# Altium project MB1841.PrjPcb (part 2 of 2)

## Sheet STLink_V3EC.SchDoc: STLINK-V3EC
size A3; Date: Not used; ApprovedBy: Not used; CheckedBy: Not used; Author: Not used; CompanyName: STMicroelectronics; DrawnBy: Not used; Engineer: Not used; Organization: Not used; Address1: Not used; Address2: Not used; Address3: Not used; Address4: Not used; DocumentNumber: 8; Revision: Not used; SheetNumber: 8; SheetTotal: 9
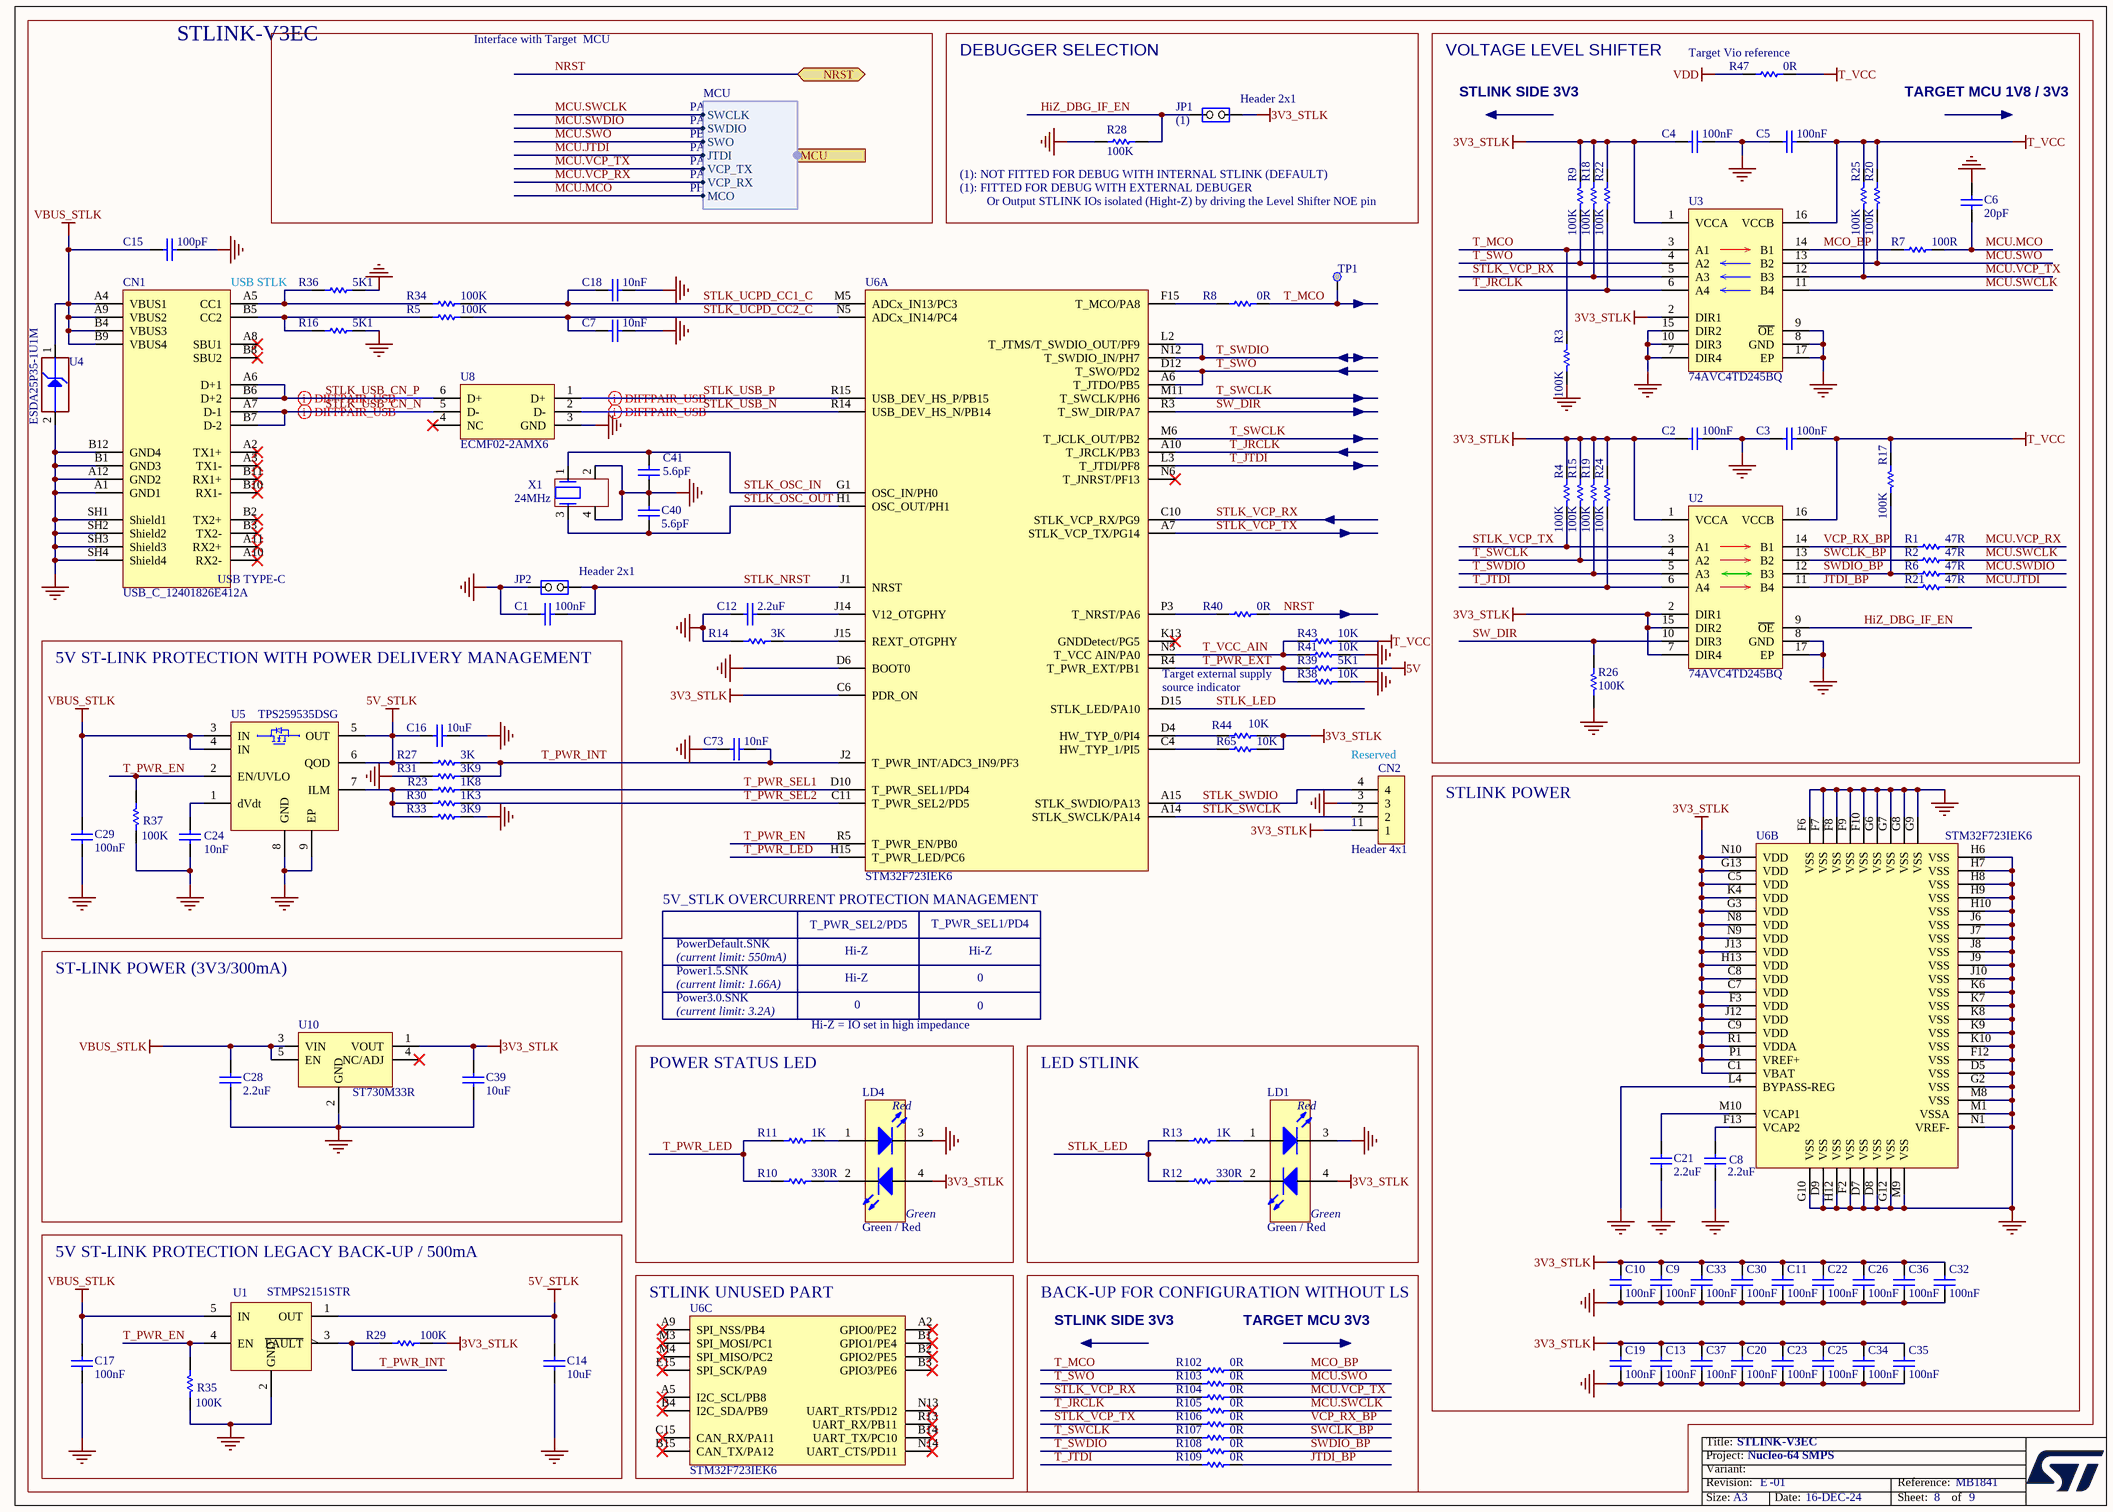
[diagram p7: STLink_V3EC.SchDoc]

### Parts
C1  value 100nF  [C0402]  (hidden comment: Capacitor)
C2  value 100nF  [C0402]  (hidden comment: Capacitor)
C3  value 100nF  [C0402]  (hidden comment: Capacitor)
C4  value 100nF  [C0402]  (hidden comment: Capacitor)
C5  value 100nF  [C0402]  (hidden comment: Capacitor)
C6  value 20pF  [C0402]  (hidden comment: Capacitor)
C7  value 10nF  [C0402]  (hidden comment: Capacitor)
C8  value 2.2uF  [C0402]  (hidden comment: Capacitor)
C9  value 100nF  [C0402]  (hidden comment: Capacitor)
C10  value 100nF  [C0402]  (hidden comment: Capacitor)
C11  value 100nF  [C0402]  (hidden comment: Capacitor)
C12  value 2.2uF  [C0402]  (hidden comment: Capacitor)
C13  value 100nF  [C0402]  (hidden comment: Capacitor)
C14  value 10uF  [C0603]  (hidden comment: Capacitor)
C15  value 100pF  [C0402]  (hidden comment: Capacitor)
C16  value 10uF  [C0603]  (hidden comment: Capacitor)
C17  value 100nF  [C0402]  (hidden comment: Capacitor)
C18  value 10nF  [C0402]  (hidden comment: Capacitor)
C19  value 100nF  [C0402]  (hidden comment: Capacitor)
C20  value 100nF  [C0402]  (hidden comment: Capacitor)
C21  value 2.2uF  [C0402]  (hidden comment: Capacitor)
C22  value 100nF  [C0402]  (hidden comment: Capacitor)
C23  value 100nF  [C0402]  (hidden comment: Capacitor)
C24  value 10nF  [C0402]  (hidden comment: Capacitor)
C25  value 100nF  [C0402]  (hidden comment: Capacitor)
C26  value 100nF  [C0402]  (hidden comment: Capacitor)
C28  value 2.2uF  [C0805]  (hidden comment: Capacitor)
C29  value 100nF  [C0402]  (hidden comment: Capacitor)
C30  value 100nF  [C0402]  (hidden comment: Capacitor)
C32  value 100nF  [C0402]  (hidden comment: Capacitor)
C33  value 100nF  [C0402]  (hidden comment: Capacitor)
C34  value 100nF  [C0402]  (hidden comment: Capacitor)
C35  value 100nF  [C0402]  (hidden comment: Capacitor)
C36  value 100nF  [C0402]  (hidden comment: Capacitor)
C37  value 100nF  [C0402]  (hidden comment: Capacitor)
C39  value 10uF  [C0603]  (hidden comment: Capacitor)
C40  value 5.6pF  [C0402]  (hidden comment: Capacitor)
C41  value 5.6pF  [C0402]  (hidden comment: Capacitor)
C73  value 10nF  [C0402]  (hidden comment: Capacitor)
CN1  value USB_C_12401826E412A  [CON_USB-TYPEC_AMPHENOL_12401826E412A]  (hidden comment: USB_TYPE_C_Receptacle)
CN2  Header 4x1  [CON_SAMTEC_TSW-104-07-G-S]
JP1  value Header 2x1  [CON_SAMTEC_TSW-102-07-G-S]  (hidden comment: Jumper_Header 2x1)
JP2  value Header 2x1  [CON_SAMTEC_TSW-102-07-G-S]  (hidden comment: Jumper_Header 2x1)
LD1  value Green / Red  [LED_BI-GR_WE-150141SV73110]  (hidden comment: LED_BICOLOR)
LD4  value Green / Red  [LED_BI-GR_WE-150141SV73110]  (hidden comment: LED_BICOLOR)
R1  value 47R  [R0402]  (hidden comment: Resistor)
R2  value 47R  [R0402]  (hidden comment: Resistor)
R3  value 100K  [R0402]  (hidden comment: Resistor)
R4  value 100K  [R0402]  (hidden comment: Resistor)
R5  value 100K  [R0402]  (hidden comment: Resistor)
R6  value 47R  [R0402]  (hidden comment: Resistor)
R7  value 100R  [R0402]  (hidden comment: Resistor)
R8  value 0R  [R0402]  (hidden comment: Resistor)
R9  value 100K  [R0402]  (hidden comment: Resistor)
R10  value 330R  [R0402]  (hidden comment: Resistor)
R11  value 1K  [R0402]  (hidden comment: Resistor)
R12  value 330R  [R0402]  (hidden comment: Resistor)
R13  value 1K  [R0402]  (hidden comment: Resistor)
R14  value 3K  [R0402]  (hidden comment: Resistor)
R15  value 100K  [R0402]  (hidden comment: Resistor)
R16  value 5K1  [R0402]  (hidden comment: Resistor)
R17  value 100K  [R0402]  (hidden comment: Resistor)
R18  value 100K  [R0402]  (hidden comment: Resistor)
R19  value 100K  [R0402]  (hidden comment: Resistor)
R20  value 100K  [R0402]  (hidden comment: Resistor)
R21  value 47R  [R0402]  (hidden comment: Resistor)
R22  value 100K  [R0402]  (hidden comment: Resistor)
R23  value 1K8  [R0402]  (hidden comment: Resistor)
R24  value 100K  [R0402]  (hidden comment: Resistor)
R25  value 100K  [R0402]  (hidden comment: Resistor)
R26  value 100K  [R0402]  (hidden comment: Resistor)
R27  value 3K  [R0402]  (hidden comment: Resistor)
R28  value 100K  [R0402]  (hidden comment: Resistor)
R29  value 100K  [R0402]  (hidden comment: Resistor)
R30  value 1K3  [R0402]  (hidden comment: Resistor)
R31  value 3K9  [R0402]  (hidden comment: Resistor)
R33  value 3K9  [R0402]  (hidden comment: Resistor)
R34  value 100K  [R0402]  (hidden comment: Resistor)
R35  value 100K  [R0402]  (hidden comment: Resistor)
R36  value 5K1  [R0402]  (hidden comment: Resistor)
R37  value 100K  [R0402]  (hidden comment: Resistor)
R38  value 10K  [R0402]  (hidden comment: Resistor)
R39  value 5K1  [R0402]  (hidden comment: Resistor)
R40  value 0R  [R0402]  (hidden comment: Resistor)
R41  value 10K  [R0402]  (hidden comment: Resistor)
R43  value 10K  [R0402]  (hidden comment: Resistor)
R44  value 10K  [R0402]  (hidden comment: Resistor)
R47  value 0R  [R0402]  (hidden comment: Resistor)
R65  value 10K  [R0402]  (hidden comment: Resistor)
R102  value 0R  [R0402]  (hidden comment: Resistor)
R103  value 0R  [R0402]  (hidden comment: Resistor)
R104  value 0R  [R0402]  (hidden comment: Resistor)
R105  value 0R  [R0402]  (hidden comment: Resistor)
R106  value 0R  [R0402]  (hidden comment: Resistor)
R107  value 0R  [R0402]  (hidden comment: Resistor)
R108  value 0R  [R0402]  (hidden comment: Resistor)
R109  value 0R  [R0402]  (hidden comment: Resistor)
TP1  Test Point  [TP_SMD_1MM]  (value not drawn)  (no BOM)
U1  STMPS2151STR  [MOS_SOT23-5L]
U2  74AVC4TD245BQ  [ICC_DHVQFN16-EPAD_SOT763-1_2P5X3P5_H0P85_P050]
U3  74AVC4TD245BQ  [ICC_DHVQFN16-EPAD_SOT763-1_2P5X3P5_H0P85_P050]
U4  value ESDA25P35-1U1M  [ESD_QFN1610_2N_1K_2A]  (hidden comment: ESD-TRANSIL)
U5  TPS259535DSG  [ICC_WSON8-EPAD_2X2_P050]
U6  value STM32F723IEK6  [ICC_UFBGA201_176+25_10X10_P065]  (hidden comment: STLINK-V3EC)  (parts A,B,C of 3)
U8  ECMF02-2AMX6  [ESD_QFN-6L_1P7X1P5_P050]
U10  ST730M33R  [ICC_SOT23-5L_H1P45]
X1  value 24MHz  [CRY_NX2016SA_4P]  (hidden comment: XTAL_4_PINS)

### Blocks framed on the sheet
DEBUGGER SELECTION: JP1 R28
VOLTAGE LEVEL SHIFTER: C2-C6 R1-R4 R6 R7 R9 R15 R17-R22 R24-R26 R47 U2 U3
5V ST-LINK PROTECTION WITH POWER DELIVERY MANAGEMENT: C16 C24 C29 R23 R27 R30 R31 R33 R37 U5
STLINK POWER: C8-C11 C13 C19-C23 C25 C26 C30 C32-C37 U6
ST-LINK POWER (3V3/300mA): C28 C39 U10
POWER STATUS LED: LD4 R10 R11
LED STLINK: LD1 R12 R13
5V ST-LINK PROTECTION LEGACY BACK-UP / 500mA: C14 C17 R29 R35 U1
STLINK UNUSED PART: U6
BACK-UP FOR CONFIGURATION WITHOUT LS: R102-R109

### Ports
MCU (harness MCU), NRST (bidir)

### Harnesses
MCU: SWCLK, SWDIO, SWO, JTDI, VCP_RX, VCP_TX, MCO

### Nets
3V3_STLK: C2.2 C4.2 C9.1 C10.1 C11.1 C13.1 C19.1 C20.1 C22.1 C23.1 C25.1 C26.1 C30.1 C32.1 C33.1 C34.1 C35.1 C36.1 C37.1 C39.2 CN2.1 JP1.1(COMMON) LD1.4(Green_anode) LD4.4(Green_anode) R4.2 R9.2 R15.2 R18.2 R19.1 R22.2 R24.1 R29.2 R44.2 R65.2 U2.1(VCCA) U2.2(DIR1) U2.7(DIR4) U2.15(DIR2) U3.1(VCCA) U3.2(DIR1) U6.C1(VBAT) U6.C5(VDD) U6.C6(PDR_ON) U6.C7(VDD) U6.C8(VDD) U6.C9(VDD) U6.F3(VDD) U6.G3(VDD) U6.G13(VDD) U6.H13(VDD) U6.J12(VDD) U6.J13(VDD) U6.K4(VDD) U6.N8(VDD) U6.N9(VDD) U6.N10(VDD) U6.P1(VREF+) U6.R1(VDDA) U10.1(VOUT)
5V: R39.2
5V_STLK: C14.2 C16.2 R27.1 U1.1(OUT) U5.5(OUT) U5.6(QOD)
GND: C1.1 C2.1 C3.2 C4.1 C5.1 C6.2 C7.2 C8.1 C9.2 C10.2 C11.2 C12.1 C13.2 C14.1 C15.2 C16.1 C17.1 C18.2 C19.2 C20.2 C21.1 C22.2 C23.2 C24.1 C25.2 C26.2 C28.1 C29.1 C30.2 C32.2 C33.2 C34.2 C35.2 C36.2 C37.2 C39.1 C40.2 C41.2 C73.2 CN1.A1(GND1) CN1.A12(GND2) CN1.B1(GND3) CN1.B12(GND4) CN1.SH1(Shield1) CN1.SH2(Shield2) CN1.SH3(Shield3) CN1.SH4(Shield4) CN2.3 JP2.2(NO) LD1.3(RED_cathode) LD4.3(RED_cathode) R3.1 R14.2 R16.2 R26.1 R28.1 R31.2 R33.2 R35.1 R36.2 R37.1 R38.2 R41.2 U1.2(GND) U2.8(GND) U2.17(EP) U3.7(DIR4) U3.8(GND) U3.9(~{OE}) U3.10(DIR3) U3.15(DIR2) U3.17(EP) U4.2(GND) U5.8(GND) U5.9(EP) U6.D5(VSS) U6.D6(BOOT0) U6.D7(VSS) U6.D8(VSS) U6.D9(VSS) U6.F2(VSS) U6.F6(VSS) U6.F7(VSS) U6.F8(VSS) U6.F9(VSS) U6.F10(VSS) U6.F12(VSS) U6.G2(VSS) U6.G6(VSS) U6.G7(VSS) U6.G8(VSS) U6.G9(VSS) U6.G10(VSS) U6.G12(VSS) U6.H6(VSS) U6.H7(VSS) U6.H8(VSS) U6.H9(VSS) U6.H10(VSS) U6.H12(VSS) U6.J6(VSS) U6.J7(VSS) U6.J8(VSS) U6.J9(VSS) U6.J10(VSS) U6.K6(VSS) U6.K7(VSS) U6.K8(VSS) U6.K9(VSS) U6.K10(VSS) U6.L4(BYPASS-REG) U6.M1(VSSA) U6.M8(VSS) U6.M9(VSS) U6.N1(VREF-) U8.3(GND) U10.2(GND) X1.2 X1.4
T_VCC: C3.1 C5.2 R17.2 R20.2 R25.2 R43.2 R47.2 U2.16(VCCB) U3.16(VCCB)
VBUS_STLK: C15.1 C17.2 C28.2 C29.2 CN1.A4(VBUS1) CN1.A9(VBUS2) CN1.B4(VBUS3) CN1.B9(VBUS4) U1.5(IN) U4.1(IO1) U5.3(IN) U5.4(IN) U10.3(VIN) U10.5(EN)
VDD: R47.1
HiZ_DBG_IF_EN: JP1.2(NO) R28.2 U2.9(~{OE})
JTDI_BP: R21.1 R109.2 U2.11(B4)
MCO_BP: R7.1 R102.2 U3.14(B1)
MCU.JTDI: R21.2 ; port MCU.JTDI
MCU.MCO: C6.1 R7.2 ; port MCU.MCO
MCU.SWCLK: R2.2 R105.2 U3.11(B4) ; port MCU.SWCLK
MCU.SWDIO: R6.2 ; port MCU.SWDIO
MCU.SWO: R20.1 R103.2 U3.13(B2) ; port MCU.SWO
MCU.VCP_RX: R1.2 ; port MCU.VCP_RX
MCU.VCP_TX: R25.1 R104.2 U3.12(B3) ; port MCU.VCP_TX
NRST: R40.2 ; port NRST
STLK_LED: R12.1 R13.2 U6.D15(STLK_LED/PA10)
STLK_NRST: C1.2 JP2.1(COMMON) U6.J1(NRST)
STLK_OSC_IN: C41.1 U6.G1(OSC_IN/PH0) X1.1
STLK_OSC_OUT: C40.1 U6.H1(OSC_OUT/PH1) X1.3
STLK_SWCLK: CN2.2 U6.A14(STLK_SWCLK/PA14)
STLK_SWDIO: CN2.4 U6.A15(STLK_SWDIO/PA13)
STLK_UCPD_CC1_C: C18.1 R34.2 U6.M5(ADCx_IN13/PC3)
STLK_UCPD_CC2_C: C7.1 R5.2 U6.N5(ADCx_IN14/PC4)
STLK_USB_CN_N: CN1.A7(D-1) CN1.B7(D-2) U8.5(D-)
STLK_USB_CN_P: CN1.A6(D+1) CN1.B6(D+2) U8.6(D+)
STLK_USB_N: U6.R14(USB_DEV_HS_N/PB14) U8.2(D-)
STLK_USB_P: U6.R15(USB_DEV_HS_P/PB15) U8.1(D+)
STLK_VCP_RX: R18.1 R104.1 U3.5(A3) U6.C10(STLK_VCP_RX/PG9)
STLK_VCP_TX: R4.1 R106.1 U2.3(A1) U6.A7(STLK_VCP_TX/PG14)
SW_DIR: R26.2 U2.10(DIR3) U6.R3(T_SW_DIR/PA7)
SWCLK_BP: R2.1 R107.2 U2.13(B2)
SWDIO_BP: R6.1 R17.1 R108.2 U2.12(B3)
T_JRCLK: R22.1 R105.1 U3.6(A4) U6.A10(T_JRCLK/PB3)
T_JTDI: R24.2 R109.1 U2.6(A4) U6.L3(T_JTDI/PF8)
T_MCO: R3.2 R8.2 R102.1 TP1.1 U3.3(A1)
T_PWR_EN: R35.2 R37.2 U1.4(EN) U5.2(EN/UVLO) U6.R5(T_PWR_EN/PB0)
T_PWR_EXT: R38.1 R39.1 U6.R4(T_PWR_EXT/PB1)
T_PWR_INT: C73.1 R27.2 R29.1 R31.1 U1.3(~{FAULT}) U6.J2(T_PWR_INT/ADC3_IN9/PF3)
T_PWR_LED: R10.2 R11.2 U6.H15(T_PWR_LED/PC6)
T_PWR_SEL1: R23.2 U6.D10(T_PWR_SEL1/PD4)
T_PWR_SEL2: R30.2 U6.C11(T_PWR_SEL2/PD5)
T_SWCLK: R15.1 R107.1 U2.4(A2) U6.M6(T_JCLK_OUT/PB2) U6.M11(T_SWCLK/PH6)
T_SWDIO: R19.2 R108.1 U2.5(A3) U6.L2(T_JTMS/T_SWDIO_OUT/PF9) U6.N12(T_SWDIO_IN/PH7)
T_SWO: R9.1 R103.1 U3.4(A2) U6.A6(T_JTDO/PB5) U6.D12(T_SWO/PD2)
T_VCC_AIN: R41.1 R43.1 U6.N3(T_VCC_AIN/PA0)
VCP_RX_BP: R1.1 R106.2 U2.14(B1)
NetC8_2: C8.2 U6.F13(VCAP2)
NetC12_2: C12.2 U6.J14(V12_OTGPHY)
NetC21_2: C21.2 U6.M10(VCAP1)
NetC24_2: C24.2 U5.1(dVdt)
NetCN1_A5: CN1.A5(CC1) R34.1 R36.1
NetCN1_B5: CN1.B5(CC2) R5.1 R16.1
NetLD1_1: LD1.1(Red_anode) R13.1
NetLD1_2: LD1.2(Green_cathode) R12.2
NetLD4_1: LD4.1(Red_anode) R11.1
NetLD4_2: LD4.2(Green_cathode) R10.1
NetR8_1: R8.1 U6.F15(T_MCO/PA8)
NetR14_1: R14.1 U6.J15(REXT_OTGPHY)
NetR23_1: R23.1 R30.1 R33.1 U5.7(ILM)
NetR40_1: R40.1 U6.P3(T_NRST/PA6)
NetR44_1: R44.1 U6.D4(HW_TYP_0/PI4)
NetR65_1: R65.1 U6.C4(HW_TYP_1/PI5)

Not connected (* = marked no-connect by the designer): CN1 A2(TX1+)* A3(TX1-)* A8(SBU1)* A10(RX2-)* A11(RX2+)* B2(TX2+)* B3(TX2-)* B8(SBU2)* B10(RX1-)* B11(RX1+)*; U6 A2(GPIO0/PE2)* A5(I2C_SCL/PB8)* A9(SPI_NSS/PB4)* B1(GPIO1/PE4)* B2(GPIO2/PE5)* B3(GPIO3/PE6)* B4(I2C_SDA/PB9)* B14(UART_TX/PC10)* B15(CAN_TX/PA12)* C15(CAN_RX/PA11)* E15(SPI_SCK/PA9)* K13(GNDDetect/PG5)* M3(SPI_MOSI/PC1)* M4(SPI_MISO/PC2)* N6(T_JNRST/PF13)* N13(UART_RTS/PD12)* N14(UART_CTS/PD11)* R13(UART_RX/PB11)*; U8 4(NC)*; U10 4(NC/ADJ)*

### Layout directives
differential pair; rule Impedance Constraint [Min = 85.00    Max = 95.00    ]: STLK_USB_CN_N, STLK_USB_CN_P, STLK_USB_N, STLK_USB_P

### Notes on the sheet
- STLINK-V3EC
- Interface with Target  MCU
- PA14
- STLINK SIDE 3V3
- (near R47) Target Vio reference
- TARGET MCU 1V8 / 3V3
- PA13
- PB3
- PA15
- PA10
- PA9
- (near R28) (1): NOT FITTED FOR DEBUG WITH INTERNAL STLINK (DEFAULT)
- (near JP1) (1)
- PH0
- (near R28) (1): FITTED FOR DEBUG WITH EXTERNAL DEBUGER
- Or Output STLINK IOs isolated (Hight-Z) by driving the Level Shifter NOE pin
- (near CN1) USB STLK
- Target external supply
- (near U6) source indicator
- (near CN2) Reserved
- (near CN2) 1
- (near U6) 5V_STLK OVERCURRENT PROTECTION MANAGEMENT
- (current limit: 550mA)
- (current limit: 1.66A)
- Power1.5.SNK
- PowerDefault.SNK
- T_PWR_SEL2/PD5
- Hi-Z
- T_PWR_SEL1/PD4
- 0
- (current limit: 3.2A)
- Power3.0.SNK
- Hi-Z = IO set in high impedance
- TARGET MCU 3V3

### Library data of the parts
C1-C5 C9-C11 C13 C19 C20 C22 C23 C25 C26 C30 C32-C37 = MCD-00006: Capacitor, MLCC, 100nF, 16V, X7R, +/-10%, 0402, T=0.5mm; Manufacturer_Part_Number: CC0402KRX7R7BB104; Manufacturer: YAGEO; Part_Preference: Recommended; Order_Code_RS: 616-9701; Component_Country_Of_Origin: China; ShowFields: YES; ID: 2474
C6 = MCD-00016: Capacitor, MLCC, 20pF, 50V, NPO, +/- 5%, 0402, T=0.5mm; Manufacturer_Part_Number: CC0402JRNPO9BN200; Manufacturer: YAGEO; Part_Preference: Recommended; Component_Country_Of_Origin: China; ShowFields: YES; ID: 2479
C7 C18 C24 = MCD-02198: Capacitor, MLCC, 10nF, 50V, X7R, +/-10%, 0402, T=0.5mm; Part_Preference: Recommended; Manufacturer: YAGEO; Manufacturer_Part_Number: CC0402KRX7R9BB103; Order_Code_RS: 6169644; Component_Country_Of_Origin: China; ShowFields: YES; ID: 4298
C8 C12 C21 = MCD-02606: Capacitor, MLCC, 2.2uF, 6.3V, X5R, +/-10%, 0402, T=0.5mm; Part_Preference: Recommended; Manufacturer: YAGEO; Manufacturer_Part_Number: CC0402KRX5R5BB225; Order_Code_RS: 1992205; ShowFields: YES; ID: 4712
C14 C16 C39 = MCD-00099: Capacitor, MLCC, 10uF, 10V, X5R, +/-10%, 0603, T=0.8mm; Part_Preference: Recommended; Manufacturer: MURATA; Manufacturer_Part_Number: GRM188R61A106KE69D; Order_Code_RS: 170-6168; Component_Country_Of_Origin: Japan; ShowFields: YES; ID: 2770
C15 = MCD-00205: Capacitor, MLCC, 100pF, 50V, NPO, +/-5%, 0402, T=0.5mm; Part_Preference: Recommended; Manufacturer: YAGEO; Manufacturer_Part_Number: CC0402JRNPO9BN101; Component_Country_Of_Origin: China; ShowFields: YES; ID: 2658
C17 C29 = MCD-02355: Capacitor, MLCC, 100nF, 25V, X7R, +/-10%, 0402, T=0.5mm; Part_Preference: Recommended; Manufacturer: WALSIN; Manufacturer_Part_Number: 0402B104K250CT; Order_Code_RS: 176-3114; Component_Country_Of_Origin: Unknown; ShowFields: YES; ID: 4461
C28 = MCD-02372: Capacitor, MLCC, 2.2uF, 25V, X7R, +/-10%, 0805, T=1,25mm; Manufacturer_Part_Number: GRM21BR71E225KE11L; Manufacturer: MURATA; Part_Preference: Recommended; Component_Country_Of_Origin: Japan; ShowFields: YES; ID: 4478
C40 C41 = MCD-01374: Capacitor, MLCC, 5.6pF, 50V, NPO, +/-0.1pF, 0402, T=0.5mm; Part_Preference: Recommended; Manufacturer: YAGEO; Manufacturer_Part_Number: CC0402BRNPO9BN5R6; Component_Country_Of_Origin: China; ShowFields: YES; ID: 3474
C73 = MCD-00011: Capacitor, MLCC, 10nF, 16V, X7R, +/-10%, 0402, T=0.5mm; Part_Preference: Recommended; Manufacturer: YAGEO; Manufacturer_Part_Number: CC0402KRX7R7BB103; Order_Code_RS: 3019275; Component_Country_Of_Origin: China; ShowFields: YES; ID: 2469
CN1 = MCD-03232: USB_TypeC, 24 pins, RA, SMD, T=2.96mm (USB Certified 3.1); Part_Type: Connector; Part_Preference: Recommended; Manufacturer: AMPHENOL ICC; Manufacturer_Part_Number: 12401826E412A; ShowFields: YES; ID: 5348
CN2 = MCD-00029: Header, 4x1, 2.54mm, VR, TH, T=5.84mm/2.54mm; Manufacturer_Part_Number: TSW-104-07-G-S; Manufacturer: SAMTEC; Part_Type: Connector; Part_Preference: Recommended; Order_Code_RS: 161-2261; Component_Country_Of_Origin: China, Costa Rica, Malaysia, United States, Vietnam; ShowFields: YES; ID: 2487
JP1 JP2 = MCD-00045: Header, 2x1, 2.54mm, VR, TH, T=5.84mm/2.54mm; Part_Preference: Recommended; Part_Type: Connector; Manufacturer: SAMTEC; Manufacturer_Part_Number: TSW-102-07-G-S; Full_Alternate_Internal_Part_Number: MCD-02390; Order_Code_RS: 155-5312; Component_Country_Of_Origin: China, Costa Rica, Malaysia, United States, Vietnam; ShowFields: YES; ID: 2545
LD1 LD4 = MCD-02631: LED Bicolor, Green/Red, 2V, 20mA,  4-PLCC; Part_Type: Display; Part_Preference: Recommended; Manufacturer: WURTH ELEKTRONIK; Manufacturer_Part_Number: 150141SV73110; Order_Code_RS: 184-6963; Component_Country_Of_Origin: China; ShowFields: YES; ID: 4737
R1 R2 R6 R21 = MCD-00481: Resistor, 47R, 0402, +/-1%, 1/16W; Part_Preference: Recommended; Manufacturer: YAGEO; Manufacturer_Part_Number: RC0402FR-0747RL; Component_Country_Of_Origin: China; ShowFields: YES; ID: 2796
R3 R4 R9 R15 R17-R20 R22 R24-R26 R28 R29 R35 R37 = MCD-00059: Resistor, 100K, 0402, +/-1%, 1/16W; Manufacturer_Part_Number: RC0402FR-07100KL; Manufacturer: YAGEO; Part_Preference: Recommended; Component_Country_Of_Origin: China; ShowFields: YES; ID: 2533
R5 R34 = MCD-00059: Resistor, 100K, 0402, +/-1%, 1/16W; Part_Preference: Recommended; Manufacturer: YAGEO; Manufacturer_Part_Number: RC0402FR-07100KL; Component_Country_Of_Origin: China; ShowFields: YES; ID: 2533
R7 = MCD-00067: Resistor, 100R, 0402, +/- 1%, 1/16W; Part_Preference: Recommended; Manufacturer: YAGEO; Manufacturer_Part_Number: RC0402FR-07100RL; Component_Country_Of_Origin: China; ShowFields: YES; ID: 2527
R8 R40 R47 R102-R109 = MCD-00052: Resistor, 0R, 0402, +/-5%, 1/16W; Part_Preference: Recommended; Manufacturer: YAGEO; Manufacturer_Part_Number: RC0402JR-070RL; Order_Code_RS: 618-5804; Component_Country_Of_Origin: China; ShowFields: YES; ID: 2540
R10 R12 = MCD-00062: Resistor, 330R, 0402, +/-1%, 1/16W; Part_Preference: Recommended; Manufacturer: YAGEO; Manufacturer_Part_Number: RC0402FR-07330RL; Component_Country_Of_Origin: China; ShowFields: YES; ID: 2529
R11 R13 = MCD-02665: Resistor, 1K, 0402, +/-0.1%, 1/16W, +/-25ppm/°C; Part_Preference: Recommended; Manufacturer: YAGEO; Manufacturer_Part_Number: RT0402BRD071KL; Order_Code_RS: 199-1298; ShowFields: YES; ID: 4771
R14 = MCD-00185: Resistor, 3K, 0402, +/-1%, 1/16W; Manufacturer_Part_Number: RC0402FR-073KL; Manufacturer: YAGEO; Part_Preference: Recommended; Component_Country_Of_Origin: China; ShowFields: YES; ID: 2682
R16 R36 R39 = MCD-00333: Resistor, 5K1, 0402, +/-1%, 1/16W; Part_Preference: Recommended; Manufacturer: YAGEO; Manufacturer_Part_Number: RC0402FR-075K1L; Component_Country_Of_Origin: China; ShowFields: YES; ID: 2944
R23 = MCD-00409: Resistor, 1K8, 0402, +/-1%, 1/16W; Part_Preference: Recommended; Manufacturer: YAGEO; Manufacturer_Part_Number: RC0402FR-071K8L; Component_Country_Of_Origin: China; ShowFields: YES; ID: 2871
R27 = MCD-00185: Resistor, 3K, 0402, +/-1%, 1/16W; Part_Preference: Recommended; Manufacturer: YAGEO; Manufacturer_Part_Number: RC0402FR-073KL; Component_Country_Of_Origin: China; ShowFields: YES; ID: 2682
R30 = MCD-00381: Resistor, 1K3, 0402, +/-1%, 1/16W; Part_Preference: Recommended; Manufacturer: YAGEO; Manufacturer_Part_Number: RC0402FR-071K3L; Component_Country_Of_Origin: China; ShowFields: YES; ID: 2898
R31 R33 = MCD-02455: Resistor, 3K9, 0402, +/-1%, 1/16W, +/-100ppm/°C; Part_Preference: Recommended; Manufacturer: YAGEO; Manufacturer_Part_Number: RC0402FR-073K9L; Order_Code_RS: 198-7783; Component_Country_Of_Origin: China; ShowFields: YES; ID: 4561
R38 R41 R43 R44 R65 = MCD-00053: Resistor, 10K, 0402, +/-1%, 1/16W; Manufacturer_Part_Number: RC0402FR-0710KL; Manufacturer: YAGEO; BMS_Part_Number: 9131590; Part_Preference: Recommended; Component_Country_Of_Origin: China; ShowFields: YES; ID: 2539
TP1 = MCD-00074: Test Point 1mm; Part_Type: Misc; Part_Preference: Recommended; ShowFields: YES; ID: 2518
U1 = MCD-00159: IC, Enhanced single channel power switches; Part_Preference: Recommended; Manufacturer: STMICROELECTRONICS; BMS_Part_Number: 9159009; Order_Code_RS: 165-5516; Component_Country_Of_Origin: Malaysia; ShowFields: YES; ID: 2708
U2 U3 = MCD-01945: 4-bit dual supply translating transceiver with configurable voltage translation; 3-state; Part_Type: IC; Manufacturer_Part_Number: 74AVC4TD245BQ,115; Manufacturer: NEXPERIA; Part_Preference: Recommended; Full_Alternate_Internal_Part_Number: MCD-03085; Component_Country_Of_Origin: Thailand; ShowFields: YES; ID: 4045
U4 = MCD-01207: High power Transient voltage suppressor:25V/35A EOS and ESD transients protection.; Part_Type: Diode; Manufacturer: STMICROELECTRONICS; BMS_Part_Number: 9179045; Part_Preference: Recommended; Manufacturer_HQ_COO: EU; Component_Country_Of_Origin: China; ShowFields: YES; ID: 3289
U5 = MCD-02532: IC, eFuse with Fast Overvoltage Protection 2.7V to 18V 4A 34mOhm 8-Pin WSON; Part_Preference: Recommended; Manufacturer: TEXAS INSTRUMENTS; ShowFields: YES; ID: 4638
U6 = MCD-03851: MCU, ARM Cortex-M7 32-bit, 512KB Flash, 276KB RAM, With Crypto; Part_Type: IC; Part_Preference: Recommended; Manufacturer: STMICROELECTRONICS; ShowFields: YES; ID: 5967; Component_Country_Of_Origin: Philippines
U8 = MCD-00649: Common mode filter with ESD protection for USB 2.0 interface; Part_Type: Diode; Manufacturer: STMICROELECTRONICS; BMS_Part_Number: 9151138; Part_Preference: Recommended; Manufacturer_HQ_COO: EU; Component_Country_Of_Origin: China; ShowFields: YES; ID: 3094
U10 = MCD-02514: LDO, 3.3V, 300mA, High input voltage: 2.5V to 28V, SOT23-5L; Part_Type: IC; Part_Preference: Recommended; Manufacturer: STMICROELECTRONICS; Component_Country_Of_Origin: Malaysia; ShowFields: YES; ID: 4620
X1 = MCD-01036: Crystal, 24MHz, 6pF, +/-20ppm, 80R, 2x1.6mm; BMS_Part_Number: 9157045; Part_Type: Crystal_Osc; Part_Preference: Recommended; Manufacturer: NDK; Manufacturer_Part_Number: NX2016SA-24MHZ-EXS00A-CS10820; Component_Country_Of_Origin: Unknown; ShowFields: YES; ID: 2989

## Sheet External_Debug_Interface.SchDoc: External Debuger Interface
size A4; Date: Not used; ApprovedBy: Not used; CheckedBy: Not used; Author: Not used; CompanyName: STMicroelectronics; DrawnBy: Not used; Engineer: Not used; Organization: Not used; Address1: Not used; Address2: Not used; Address3: Not used; Address4: Not used; DocumentNumber: 9; Revision: Not used; SheetNumber: 9; SheetTotal: 9
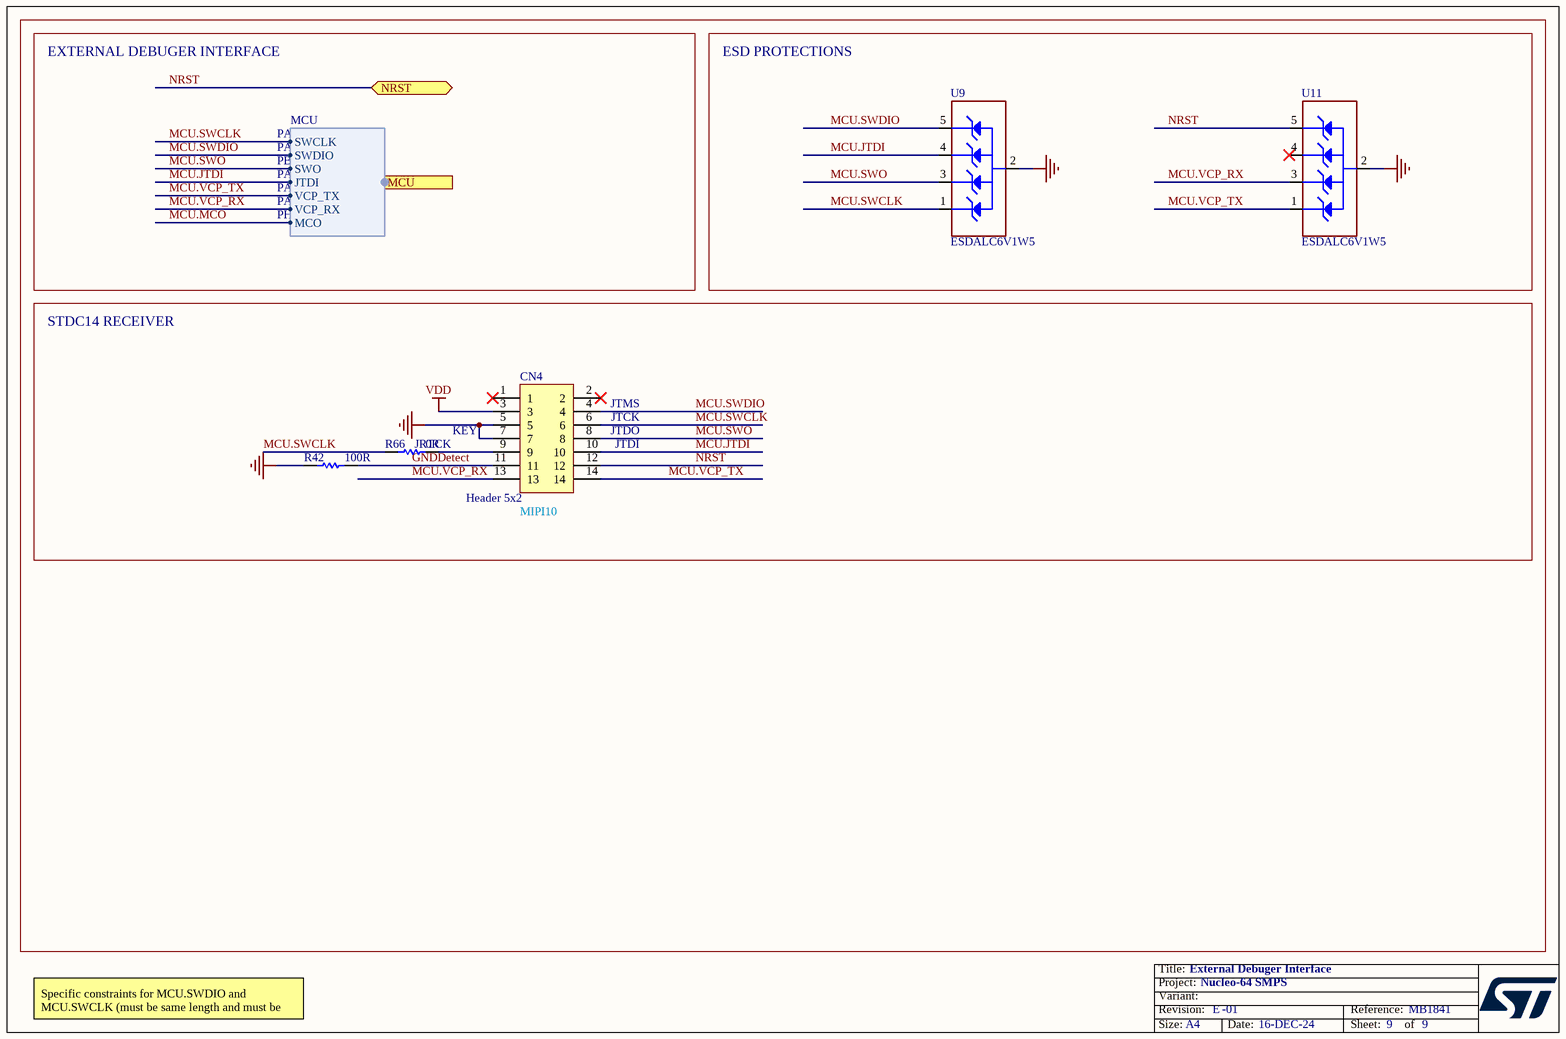
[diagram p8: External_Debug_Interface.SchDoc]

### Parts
CN4  value Header 5x2  [CON_STDC14_Receiver_MEDIUM_WITH_MIPI10_3D]  (hidden comment: Header 7x2)
R42  value 100R  [R0402]  (hidden comment: Resistor)
R66  value 0R  [R0402]  (hidden comment: Resistor)
U9  ESDALC6V1W5  [ESD_SOT323-5L]
U11  ESDALC6V1W5  [ESD_SOT323-5L]

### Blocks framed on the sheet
ESD PROTECTIONS: U9 U11
STDC14 RECEIVER: CN4 R42 R66

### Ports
MCU (harness MCU), NRST (bidir)

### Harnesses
MCU: SWCLK, SWDIO, SWO, JTDI, VCP_RX, VCP_TX, MCO

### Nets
GND: CN4.5 CN4.7 R42.1 U9.2(GND) U11.2(GND)
VDD: CN4.3
GNDDetect: CN4.11 R42.2
MCU.JTDI: CN4.10 U9.4(IO3) ; port MCU.JTDI
MCU.SWCLK: CN4.6 R66.1 U9.1(IO1) ; port MCU.SWCLK
MCU.SWDIO: CN4.4 U9.5(IO4) ; port MCU.SWDIO
MCU.SWO: CN4.8 U9.3(IO2) ; port MCU.SWO
MCU.VCP_RX: CN4.13 U11.3(IO2) ; port MCU.VCP_RX
MCU.VCP_TX: CN4.14 U11.1(IO1) ; port MCU.VCP_TX
NRST: CN4.12 U11.5(IO4) ; port NRST
NetCN4_9: CN4.9 R66.2

Not connected (* = marked no-connect by the designer): CN4 1* 2*; U11 4(IO3)*

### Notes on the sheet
- EXTERNAL DEBUGER INTERFACE
- PA14
- PA13
- PB3
- PA15
- PA10
- PA9
- PH0
- KEY
- JRTCK
- JTMS
- JTCK
- JTDO
- JTDI
- (near CN4) MIPI10
- Specific constraints for MCU.SWDIO and MCU.SWCLK (must be same length and must be Shielded).

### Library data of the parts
CN4 = MCD-01226: Header, 5x2, 1.27mm, VR, SMD, T=5.97mm/3.05mm; Part_Type: Connector; Manufacturer_Part_Number: FTSH-105-01-L-DV-K; Manufacturer: SAMTEC; Part_Preference: Recommended; Order_Code_RS: 159-2332; Component_Country_Of_Origin: China, Costa Rica, Malaysia, United States, Vietnam; ShowFields: YES; ID: 3265
R42 = MCD-00067: as R7 on sheet STLink_V3EC
R66 = MCD-00052: Resistor, 0R, 0402, +/-5%, 1/16W; Part_Preference: Recommended; Manufacturer: YAGEO; Manufacturer_Part_Number: RC0402JR-070RL; Order_Code_RS: 9232516RL; Component_Country_Of_Origin: China; ShowFields: YES; ID: 2540
U9 U11 = MCD-00136: Dual Transil array for ESD protection; BMS_Part_Number: 9151112; Part_Type: Diode; Part_Preference: Recommended; Manufacturer: STMICROELECTRONICS; Manufacturer_HQ_COO: EU; Component_Country_Of_Origin: China; ShowFields: YES; ID: 2731

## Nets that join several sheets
3V3: Arduino_extension_connectors (CN6.4 CN7.16 R49.2 SB11.1), Power (JP5.1 SB8.2 TP3.1), STM32_microcontroller_power (SB14.1 SB33.1), USB (R61.2)
5V: Arduino_extension_connectors (CN6.5 CN7.18), Power (11 pins), STLink_V3EC (R39.2)
5V_STLK: Power (JP3.1), STLink_V3EC (6 pins)
5V_UCPD: Power (JP3.9), USB (7 pins)
5V_VIN: Arduino_extension_connectors (R52.1), Power (C45.2 JP3.3 U16.2 U16.4)
AGND: Arduino_extension_connectors (CN10.32), STM32_microcontroller_power (C52.2 C53.1 SB12.2 U17.12)
AVDD: Arduino_extension_connectors (CN5.8 CN10.7), STM32_microcontroller_power (5 pins)
E5V: Arduino_extension_connectors (CN7.6), Power (JP3.5)
GND: Arduino_extension_connectors (11 pins), Power (23 pins), STM32_microcontroller_IOs (14 pins), STM32_microcontroller_power (20 pins), USB (24 pins), STLink_V3EC (119 pins), External_Debug_Interface (5 pins)
VBAT: Arduino_extension_connectors (CN7.33), STM32_microcontroller_power (C54.2 SB25.2 U17.1)
VBUS_STLK: Arduino_extension_connectors (CN10.8), Power (JP3.7), STLink_V3EC (14 pins)
VDD: Arduino_extension_connectors (CN7.5 SB9.1), Power (JP5.2), STM32_microcontroller_IOs (B1.1 B1.2), STM32_microcontroller_power (JP4.1), STLink_V3EC (R47.1), External_Debug_Interface (CN4.3)
VIN: Arduino_extension_connectors (CN6.8 CN7.24), Power (C47.2 U16.3)
ARD_D0_RX: Arduino_extension_connectors (CN9.1 CN10.37), STM32_microcontroller_IOs (SB15.2 SB34.1)
ARD_D1_TX: Arduino_extension_connectors (CN9.2 CN10.35), STM32_microcontroller_IOs (SB17.2 SB36.1)
MCU.JTDI: STM32_microcontroller_IOs (SB41.1), STLink_V3EC (R21.2), External_Debug_Interface (CN4.10 U9.4)
MCU.MCO: STM32_microcontroller_IOs (SB20.1), STLink_V3EC (C6.1 R7.2)
MCU.SWCLK: STM32_microcontroller_IOs (SB29.1), STLink_V3EC (R2.2 R105.2 U3.11), External_Debug_Interface (CN4.6 R66.1 U9.1)
MCU.SWDIO: STM32_microcontroller_IOs (SB30.1), STLink_V3EC (R6.2), External_Debug_Interface (CN4.4 U9.5)
MCU.SWO: STM32_microcontroller_IOs (SB28.2), STLink_V3EC (R20.1 R103.2 U3.13), External_Debug_Interface (CN4.8 U9.3)
MCU.VCP_RX: STM32_microcontroller_IOs (SB16.1 SB35.1), STLink_V3EC (R1.2), External_Debug_Interface (CN4.13 U11.3)
MCU.VCP_TX: STM32_microcontroller_IOs (SB26.1 SB37.1), STLink_V3EC (R25.1 R104.2 U3.12), External_Debug_Interface (CN4.14 U11.1)
NRST: Arduino_extension_connectors (CN6.3 CN7.14), STM32_microcontroller_IOs (5 pins), STLink_V3EC (R40.2), External_Debug_Interface (CN4.12 U11.5)
PA0: Arduino_extension_connectors (CN7.28 CN8.1), STM32_microcontroller_IOs (SB23.2 U17.14)
PA1: Arduino_extension_connectors (CN7.30 CN8.2), STM32_microcontroller_IOs (U17.15)
PA4: Arduino_extension_connectors (CN7.32 CN8.3), STM32_microcontroller_IOs (U17.20)
PA5: Arduino_extension_connectors (CN5.6 CN10.11 SB10.1), STM32_microcontroller_IOs (U17.21)
PA6: Arduino_extension_connectors (CN5.5 CN10.13), STM32_microcontroller_IOs (U17.22)
PA7: Arduino_extension_connectors (CN5.4 CN10.15), STM32_microcontroller_IOs (U17.23)
PA8: Arduino_extension_connectors (CN9.8 CN10.23), STM32_microcontroller_IOs (U17.41)
PA9: Arduino_extension_connectors (CN10.2), STM32_microcontroller_IOs (SB36.2 SB37.2 U17.42)
PA10: Arduino_extension_connectors (CN10.4), STM32_microcontroller_IOs (SB34.2 SB35.2 U17.43)
PA11: Arduino_extension_connectors (CN10.14), STM32_microcontroller_IOs (SB38.1)
PA12: Arduino_extension_connectors (CN10.12), STM32_microcontroller_IOs (SB39.1)
PA13: Arduino_extension_connectors (CN7.13), STM32_microcontroller_IOs (SB30.2 U17.46)
PA14: Arduino_extension_connectors (CN7.15), STM32_microcontroller_IOs (SB29.2 U17.49)
PA15: Arduino_extension_connectors (CN7.17), STM32_microcontroller_IOs (SB41.2 U17.50)
PB0: Arduino_extension_connectors (CN7.34 CN8.4), STM32_microcontroller_IOs (U17.24)
PB1: Arduino_extension_connectors (CN10.24), STM32_microcontroller_IOs (U17.25)
PB2: Arduino_extension_connectors (CN10.22), STM32_microcontroller_IOs (U17.26)
PB3: Arduino_extension_connectors (CN9.4 CN10.31), STM32_microcontroller_IOs (SB28.1 U17.55)
PB4: Arduino_extension_connectors (CN9.6 CN10.27), STM32_microcontroller_IOs (U17.56)
PB5: Arduino_extension_connectors (CN9.5 CN10.29), STM32_microcontroller_IOs (U17.57)
PB6: Arduino_extension_connectors (SB42.1), STM32_microcontroller_IOs (U17.58)
PB7: Arduino_extension_connectors (SB44.1), STM32_microcontroller_IOs (U17.59)
PB8: Arduino_extension_connectors (CN10.36), STM32_microcontroller_IOs (U17.61)
PB10: Arduino_extension_connectors (CN9.7 CN10.25), STM32_microcontroller_IOs (U17.27)
PB13: Arduino_extension_connectors (CN10.30 SB43.1), STM32_microcontroller_IOs (U17.34)
PB14: Arduino_extension_connectors (CN10.28 SB45.1), STM32_microcontroller_IOs (U17.35)
PB15: Arduino_extension_connectors (CN10.26), STM32_microcontroller_IOs (U17.36)
PC0: Arduino_extension_connectors (CN7.38 CN8.6), STM32_microcontroller_IOs (U17.8)
PC1: Arduino_extension_connectors (CN7.36 CN8.5), STM32_microcontroller_IOs (U17.9)
PC2: Arduino_extension_connectors (CN7.35), STM32_microcontroller_IOs (SB31.2 U17.10)
PC3: Arduino_extension_connectors (CN7.37), STM32_microcontroller_IOs (U17.11)
PC6: Arduino_extension_connectors (CN5.2 CN10.19), STM32_microcontroller_IOs (U17.37)
PC7: Arduino_extension_connectors (CN5.1 CN10.21), STM32_microcontroller_IOs (U17.38)
PC8: Arduino_extension_connectors (CN9.3 CN10.33), STM32_microcontroller_IOs (U17.39)
PC9: Arduino_extension_connectors (CN5.3 CN10.17), STM32_microcontroller_IOs (U17.40)
PC10: Arduino_extension_connectors (CN7.1), STM32_microcontroller_IOs (U17.51)
PC11: Arduino_extension_connectors (CN7.2), STM32_microcontroller_IOs (U17.52)
PC12: Arduino_extension_connectors (CN7.3), STM32_microcontroller_IOs (U17.53)
PC13: Arduino_extension_connectors (CN7.23), STM32_microcontroller_IOs (SB24.2 U17.2)
PC14: Arduino_extension_connectors (CN7.25), STM32_microcontroller_IOs (SB22.1)
PC15: Arduino_extension_connectors (CN7.27), STM32_microcontroller_IOs (SB18.1)
PD2: Arduino_extension_connectors (CN7.4), STM32_microcontroller_IOs (U17.54)
PH0: Arduino_extension_connectors (CN7.29), STM32_microcontroller_IOs (SB19.1)
PH1: Arduino_extension_connectors (CN7.31), STM32_microcontroller_IOs (SB21.1)
PH3_BOOT0: Arduino_extension_connectors (CN7.7), STM32_microcontroller_IOs (R54.2 U17.60)
USB_FS_N: STM32_microcontroller_IOs (SB38.2 U17.44), USB (CN3.A7 CN3.B7 U18.1 U18.6)
USB_FS_P: STM32_microcontroller_IOs (SB39.2 U17.45), USB (CN3.A6 CN3.B6 U18.3 U18.4)
VBUS_SENSE: STM32_microcontroller_IOs (SB31.1), USB (C69.2 R55.2 R56.1)

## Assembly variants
U535REQ: not fitted C14 C17 C48 C51 C57 C62 C64 C66 C72 CN2 HW110 JP2 R29 R35 R45 R48 R62 R63 R64 R102 R103 R104 R105 R106 R107 R108 R109 SB3 SB4 SB6 SB7 SB11 SB14 SB16 SB18 SB20 SB22 SB23 SB26 SB32 SB34 SB36 SB40 U1 U22 X2
U545REQ: not fitted C14 C17 C48 C51 C57 C62 C64 C66 C72 CN2 HW110 JP2 R29 R35 R45 R48 R62 R63 R64 R102 R103 R104 R105 R106 R107 R108 R109 SB3 SB4 SB6 SB7 SB11 SB14 SB16 SB18 SB20 SB22 SB23 SB26 SB32 SB34 SB36 SB40 U1 U22 X2
U575RIQ_S: not fitted C14 C17 C57 C62 C64 C66 C72 CN2 JP2 R29 R35 R45 R48 R62 R63 R64 R102 R103 R104 R105 R106 R107 R108 R109 SB6 SB7 SB11 SB14 SB16 SB18 SB19 SB20 SB21 SB22 SB23 SB26 SB32 SB34 SB36 SB40 U1 U22; alternate parts C49 -> MCD-02066, C50 -> MCD-02066
U545REQ_S: not fitted C14 C17 C57 C62 C64 C66 C72 CN2 JP2 R29 R35 R45 R48 R62 R63 R64 R102 R103 R104 R105 R106 R107 R108 R109 SB6 SB7 SB11 SB14 SB16 SB18 SB19 SB20 SB21 SB22 SB23 SB26 SB32 SB34 SB36 SB40 U1 U22; alternate parts C49 -> MCD-02066, C50 -> MCD-02066
U385RGQ: not fitted C14 C17 C48 C51 C57 C62 C64 C66 C72 CN2 HW110 R29 R35 R45 R48 R62 R63 R64 R102 R103 R104 R105 R106 R107 R108 R109 SB3 SB4 SB6 SB7 SB11 SB14 SB16 SB18 SB20 SB22 SB23 SB26 SB32 SB34 SB36 SB40 SB42 SB44 U1 U22 X2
